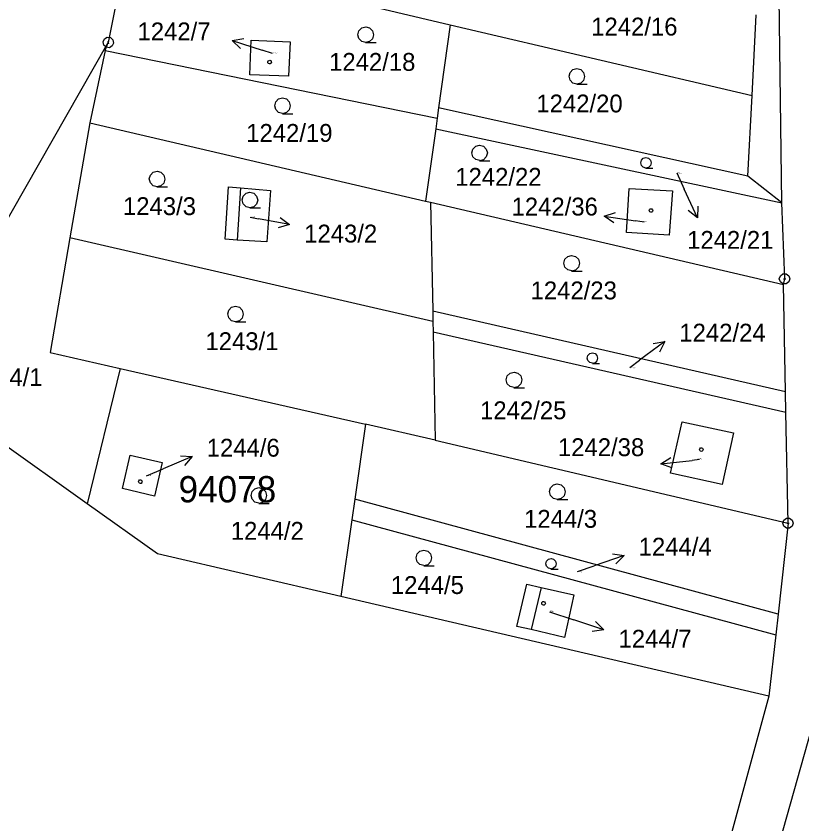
# Model space of a CAD drawing. Extents: x -806774 to -803680, y -1151731 to -1150053.
# Drawn here: x -803855.9 to -803781.2, y -1150682 to -1150605.2 of the extents above; entities that cross this region are included whole.
import ezdxf

# ---------------------------------------------------------------- set-up
doc = ezdxf.new("R2010")
doc.units = 0
for name, color, linetype in [('1', 7, 'Continuous'), ('11', 7, 'Continuous'), ('12', 7, 'Continuous'), ('2', 7, 'Continuous'), ('3', 7, 'Continuous'), ('4', 7, 'Continuous'), ('5', 7, 'Continuous'), ('7', 7, 'Continuous'), ('8', 7, 'Continuous')]:
    doc.layers.add(name, color=color, linetype=linetype)

msp = doc.modelspace()

# ---------------------------------------------------------------- linework, layer by layer
at = {"layer": '1'}
for p, q in [((-803845.41, -1150598.72), (-803847.18, -1150607.67)), ((-803783.05, -1150622.92), (-803783.39, -1150598.76)), ((-803822.55, -1150604.1), (-803814.62, -1150605.97)), ((-803785.89, -1150612.72), (-803785.49, -1150605.04)), ((-803814.62, -1150605.97), (-803815.74, -1150613.89)), ((-803814.62, -1150605.97), (-803785.89, -1150612.72)), ((-803865.58, -1150639.91), (-803847.18, -1150607.67)), ((-803847.47, -1150608.42), (-803847.18, -1150607.67)), ((-803833.69, -1150610.73), (-803833.57, -1150607.45)), ((-803833.57, -1150607.45), (-803829.86, -1150607.61)), ((-803829.86, -1150607.61), (-803830.01, -1150610.88)), ((-803847.47, -1150608.42), (-803848.93, -1150615.31)), ((-803847.47, -1150608.42), (-803815.87, -1150614.85)), ((-803830.01, -1150610.88), (-803833.69, -1150610.73)), ((-803786.3, -1150620.37), (-803785.89, -1150612.72)), ((-803815.74, -1150613.89), (-803815.87, -1150614.85)), ((-803786.3, -1150620.37), (-803815.74, -1150613.89)), ((-803815.87, -1150614.85), (-803816.01, -1150615.87)), ((-803848.93, -1150615.31), (-803850.82, -1150626.24)), ((-803848.93, -1150615.31), (-803816.99, -1150622.76)), ((-803816.01, -1150615.87), (-803816.99, -1150622.76)), ((-803816.01, -1150615.87), (-803783.05, -1150622.92)), ((-803783.05, -1150622.92), (-803786.3, -1150620.37)), ((-803836.05, -1150626.39), (-803835.72, -1150621.41)), ((-803835.72, -1150621.41), (-803834.58, -1150621.51)), ((-803834.58, -1150621.51), (-803831.74, -1150621.75)), ((-803831.74, -1150621.75), (-803832.09, -1150626.64)), ((-803797.86, -1150625.76), (-803797.59, -1150621.57)), ((-803797.59, -1150621.57), (-803793.46, -1150621.79)), ((-803793.46, -1150621.79), (-803793.78, -1150625.99)), ((-803816.99, -1150622.76), (-803816.5, -1150622.87)), ((-803816.5, -1150622.87), (-803816.29, -1150633.21)), ((-803816.5, -1150622.87), (-803782.9, -1150630.7)), ((-803782.79, -1150630.17), (-803783.05, -1150622.92)), ((-803850.82, -1150626.24), (-803852.71, -1150637.17)), ((-803816.27, -1150634.23), (-803850.82, -1150626.24)), ((-803834.92, -1150626.47), (-803836.05, -1150626.39)), ((-803832.09, -1150626.64), (-803834.92, -1150626.47)), ((-803793.78, -1150625.99), (-803797.86, -1150625.76)), ((-803782.9, -1150630.7), (-803782.79, -1150630.17)), ((-803782.71, -1150640.88), (-803782.9, -1150630.7)), ((-803816.29, -1150633.21), (-803816.27, -1150634.23)), ((-803816.29, -1150633.21), (-803782.71, -1150640.88)), ((-803816.27, -1150634.23), (-803816.26, -1150635.22)), ((-803816.26, -1150635.22), (-803816.05, -1150645.51)), ((-803782.67, -1150642.88), (-803816.26, -1150635.22)), ((-803852.71, -1150637.17), (-803846.03, -1150638.68)), ((-803846.03, -1150638.68), (-803849.18, -1150651.58)), ((-803846.03, -1150638.68), (-803822.68, -1150643.99)), ((-803849.18, -1150651.58), (-803864.14, -1150640.93)), ((-803782.67, -1150642.88), (-803782.71, -1150640.88)), ((-803782.47, -1150653.42), (-803782.67, -1150642.88)), ((-803822.68, -1150643.99), (-803823.71, -1150651.14)), ((-803816.05, -1150645.51), (-803822.68, -1150643.99)), ((-803793.67, -1150648.66), (-803792.54, -1150643.75)), ((-803792.54, -1150643.75), (-803787.65, -1150644.82)), ((-803787.65, -1150644.82), (-803788.75, -1150649.74)), ((-803816.05, -1150645.51), (-803782.47, -1150653.42)), ((-803845.83, -1150650.12), (-803845.09, -1150646.95)), ((-803845.09, -1150646.95), (-803842.04, -1150647.64)), ((-803842.04, -1150647.64), (-803842.79, -1150650.83)), ((-803788.75, -1150649.74), (-803793.67, -1150648.66)), ((-803842.79, -1150650.83), (-803845.83, -1150650.12)), ((-803842.49, -1150656.34), (-803849.18, -1150651.58)), ((-803823.71, -1150651.14), (-803824, -1150653.1)), ((-803783.42, -1150662.06), (-803823.71, -1150651.14)), ((-803824, -1150653.1), (-803825.05, -1150660.39)), ((-803824, -1150653.1), (-803783.64, -1150664.03)), ((-803782.47, -1150653.42), (-803783.42, -1150662.06)), ((-803825.05, -1150660.39), (-803842.49, -1150656.34)), ((-803808.28, -1150663.23), (-803807.34, -1150659.2)), ((-803807.34, -1150659.2), (-803805.97, -1150659.52)), ((-803805.97, -1150659.52), (-803802.86, -1150660.22)), ((-803802.86, -1150660.22), (-803803.74, -1150664.29)), ((-803784.29, -1150669.87), (-803825.05, -1150660.39)), ((-803783.42, -1150662.06), (-803783.64, -1150664.03)), ((-803806.93, -1150663.53), (-803808.28, -1150663.23)), ((-803803.74, -1150664.29), (-803806.93, -1150663.53)), ((-803783.64, -1150664.03), (-803784.29, -1150669.87)), ((-803784.29, -1150669.87), (-803800.37, -1150728.46)), ((-803785.39, -1150691.33), (-803779.86, -1150671.69))]:
    msp.add_line(p, q, dxfattribs=at)
at = {"layer": '12'}
for p, q in [((-803833.69, -1150610.73), (-803833.57, -1150607.45)), ((-803833.57, -1150607.45), (-803829.86, -1150607.61)), ((-803829.86, -1150607.61), (-803830.01, -1150610.88)), ((-803830.01, -1150610.88), (-803833.69, -1150610.73)), ((-803797.86, -1150625.76), (-803797.59, -1150621.57)), ((-803797.59, -1150621.57), (-803793.46, -1150621.79)), ((-803793.46, -1150621.79), (-803793.78, -1150625.99)), ((-803793.78, -1150625.99), (-803797.86, -1150625.76)), ((-803793.67, -1150648.66), (-803792.54, -1150643.75)), ((-803792.54, -1150643.75), (-803787.65, -1150644.82)), ((-803787.65, -1150644.82), (-803788.75, -1150649.74)), ((-803845.83, -1150650.12), (-803845.09, -1150646.95)), ((-803845.09, -1150646.95), (-803842.04, -1150647.64)), ((-803842.04, -1150647.64), (-803842.79, -1150650.83)), ((-803788.75, -1150649.74), (-803793.67, -1150648.66)), ((-803842.79, -1150650.83), (-803845.83, -1150650.12)), ((-803805.97, -1150659.52), (-803806.93, -1150663.53)), ((-803805.97, -1150659.52), (-803802.86, -1150660.22)), ((-803802.86, -1150660.22), (-803803.74, -1150664.29)), ((-803803.74, -1150664.29), (-803806.93, -1150663.53))]:
    msp.add_line(p, q, dxfattribs=at)
at = {"layer": '3'}
for points in [[(-803822.66, -1150607.66), (-803823.04, -1150607.56), (-803823.31, -1150607.29), (-803823.41, -1150606.92), (-803823.31, -1150606.55), (-803823.04, -1150606.28), (-803822.67, -1150606.18), (-803822.3, -1150606.28), (-803822.03, -1150606.55), (-803821.93, -1150606.93), (-803822.03, -1150607.31), (-803822.3, -1150607.58), (-803822.68, -1150607.68), (-803821.68, -1150607.68)], [(-803802.56, -1150611.62), (-803802.94, -1150611.52), (-803803.21, -1150611.25), (-803803.31, -1150610.88), (-803803.21, -1150610.51), (-803802.94, -1150610.24), (-803802.57, -1150610.14), (-803802.2, -1150610.24), (-803801.93, -1150610.51), (-803801.83, -1150610.89), (-803801.93, -1150611.27), (-803802.2, -1150611.54), (-803802.58, -1150611.64), (-803801.58, -1150611.64)], [(-803830.58, -1150614.42), (-803830.96, -1150614.32), (-803831.23, -1150614.05), (-803831.33, -1150613.68), (-803831.23, -1150613.31), (-803830.96, -1150613.04), (-803830.59, -1150612.94), (-803830.22, -1150613.04), (-803829.95, -1150613.31), (-803829.85, -1150613.69), (-803829.95, -1150614.07), (-803830.22, -1150614.34), (-803830.6, -1150614.44), (-803829.6, -1150614.44)], [(-803811.82, -1150618.91), (-803812.2, -1150618.81), (-803812.47, -1150618.54), (-803812.57, -1150618.17), (-803812.47, -1150617.8), (-803812.2, -1150617.53), (-803811.83, -1150617.43), (-803811.46, -1150617.53), (-803811.19, -1150617.8), (-803811.09, -1150618.18), (-803811.19, -1150618.56), (-803811.46, -1150618.83), (-803811.84, -1150618.93), (-803810.84, -1150618.93)], [(-803795.99, -1150619.61), (-803796.245, -1150619.543), (-803796.426, -1150619.362), (-803796.492, -1150619.114), (-803796.426, -1150618.866), (-803796.245, -1150618.685), (-803795.997, -1150618.618), (-803795.749, -1150618.685), (-803795.568, -1150618.866), (-803795.501, -1150619.121), (-803795.568, -1150619.376), (-803795.749, -1150619.556), (-803796.003, -1150619.623), (-803795.333, -1150619.623)], [(-803842.52, -1150621.39), (-803842.9, -1150621.29), (-803843.17, -1150621.02), (-803843.27, -1150620.65), (-803843.17, -1150620.28), (-803842.9, -1150620.01), (-803842.53, -1150619.91), (-803842.16, -1150620.01), (-803841.89, -1150620.28), (-803841.79, -1150620.66), (-803841.89, -1150621.04), (-803842.16, -1150621.31), (-803842.54, -1150621.41), (-803841.54, -1150621.41)], [(-803833.68, -1150623.39), (-803834.06, -1150623.29), (-803834.33, -1150623.02), (-803834.43, -1150622.65), (-803834.33, -1150622.28), (-803834.06, -1150622.01), (-803833.69, -1150621.91), (-803833.32, -1150622.01), (-803833.05, -1150622.28), (-803832.95, -1150622.66), (-803833.05, -1150623.04), (-803833.32, -1150623.31), (-803833.7, -1150623.41), (-803832.7, -1150623.41)], [(-803803.06, -1150629.41), (-803803.44, -1150629.31), (-803803.71, -1150629.04), (-803803.81, -1150628.67), (-803803.71, -1150628.3), (-803803.44, -1150628.03), (-803803.07, -1150627.93), (-803802.7, -1150628.03), (-803802.43, -1150628.3), (-803802.33, -1150628.68), (-803802.43, -1150629.06), (-803802.7, -1150629.33), (-803803.08, -1150629.43), (-803802.08, -1150629.43)], [(-803835.05, -1150634.24), (-803835.43, -1150634.14), (-803835.7, -1150633.87), (-803835.8, -1150633.5), (-803835.7, -1150633.13), (-803835.43, -1150632.86), (-803835.06, -1150632.76), (-803834.69, -1150632.86), (-803834.42, -1150633.13), (-803834.32, -1150633.51), (-803834.42, -1150633.89), (-803834.69, -1150634.16), (-803835.07, -1150634.26), (-803834.07, -1150634.26)], [(-803801.08, -1150638.19), (-803801.335, -1150638.123), (-803801.515, -1150637.942), (-803801.582, -1150637.694), (-803801.515, -1150637.446), (-803801.335, -1150637.265), (-803801.087, -1150637.198), (-803800.839, -1150637.265), (-803800.658, -1150637.446), (-803800.591, -1150637.701), (-803800.658, -1150637.955), (-803800.839, -1150638.136), (-803801.093, -1150638.203), (-803800.423, -1150638.203)], [(-803808.54, -1150640.51), (-803808.92, -1150640.41), (-803809.19, -1150640.14), (-803809.29, -1150639.77), (-803809.19, -1150639.4), (-803808.92, -1150639.13), (-803808.55, -1150639.03), (-803808.18, -1150639.13), (-803807.91, -1150639.4), (-803807.81, -1150639.78), (-803807.91, -1150640.16), (-803808.18, -1150640.43), (-803808.56, -1150640.53), (-803807.56, -1150640.53)], [(-803832.83, -1150651.51), (-803833.21, -1150651.41), (-803833.48, -1150651.14), (-803833.58, -1150650.77), (-803833.48, -1150650.4), (-803833.21, -1150650.13), (-803832.84, -1150650.03), (-803832.47, -1150650.13), (-803832.2, -1150650.4), (-803832.1, -1150650.78), (-803832.2, -1150651.16), (-803832.47, -1150651.43), (-803832.85, -1150651.53), (-803831.85, -1150651.53)], [(-803804.42, -1150651.15), (-803804.8, -1150651.05), (-803805.07, -1150650.78), (-803805.17, -1150650.41), (-803805.07, -1150650.04), (-803804.8, -1150649.77), (-803804.43, -1150649.67), (-803804.06, -1150649.77), (-803803.79, -1150650.04), (-803803.69, -1150650.42), (-803803.79, -1150650.8), (-803804.06, -1150651.07), (-803804.44, -1150651.17), (-803803.44, -1150651.17)], [(-803817.13, -1150657.45), (-803817.51, -1150657.35), (-803817.78, -1150657.08), (-803817.88, -1150656.71), (-803817.78, -1150656.34), (-803817.51, -1150656.07), (-803817.14, -1150655.97), (-803816.77, -1150656.07), (-803816.5, -1150656.34), (-803816.4, -1150656.72), (-803816.5, -1150657.1), (-803816.77, -1150657.37), (-803817.15, -1150657.47), (-803816.15, -1150657.47)], [(-803805.02, -1150657.76), (-803805.275, -1150657.693), (-803805.456, -1150657.512), (-803805.523, -1150657.264), (-803805.456, -1150657.016), (-803805.275, -1150656.835), (-803805.027, -1150656.768), (-803804.779, -1150656.835), (-803804.598, -1150657.016), (-803804.531, -1150657.271), (-803804.598, -1150657.525), (-803804.779, -1150657.706), (-803805.033, -1150657.773), (-803804.363, -1150657.773)]]:
    msp.add_lwpolyline(points, dxfattribs=at)
at = {"layer": '4'}
for p, q in [((-803834.58, -1150621.51), (-803834.92, -1150626.47)), ((-803805.97, -1150659.52), (-803806.93, -1150663.53))]:
    msp.add_line(p, q, dxfattribs=at)
at = {"layer": '5'}
for points in [[(-803831.989, -1150609.514), (-803831.96, -1150609.416), (-803831.866, -1150609.375), (-803831.804, -1150609.361), (-803831.716, -1150609.389), (-803831.654, -1150609.475), (-803831.651, -1150609.546), (-803831.689, -1150609.633), (-803831.754, -1150609.687), (-803831.836, -1150609.699), (-803831.924, -1150609.671), (-803831.986, -1150609.585)], [(-803795.52, -1150623.48), (-803795.42, -1150623.5), (-803795.37, -1150623.59), (-803795.35, -1150623.65), (-803795.37, -1150623.74), (-803795.45, -1150623.81), (-803795.52, -1150623.82), (-803795.61, -1150623.79), (-803795.67, -1150623.73), (-803795.69, -1150623.65), (-803795.67, -1150623.56), (-803795.59, -1150623.49)], [(-803790.72, -1150646.24), (-803790.62, -1150646.26), (-803790.57, -1150646.35), (-803790.55, -1150646.41), (-803790.57, -1150646.5), (-803790.65, -1150646.57), (-803790.72, -1150646.58), (-803790.81, -1150646.55), (-803790.87, -1150646.49), (-803790.89, -1150646.41), (-803790.87, -1150646.32), (-803790.79, -1150646.25)], [(-803844.12, -1150649.29), (-803844.02, -1150649.31), (-803843.97, -1150649.4), (-803843.95, -1150649.46), (-803843.97, -1150649.55), (-803844.05, -1150649.62), (-803844.12, -1150649.63), (-803844.21, -1150649.6), (-803844.27, -1150649.54), (-803844.29, -1150649.46), (-803844.27, -1150649.37), (-803844.19, -1150649.3)], [(-803805.74, -1150660.87), (-803805.64, -1150660.89), (-803805.59, -1150660.98), (-803805.57, -1150661.04), (-803805.59, -1150661.13), (-803805.67, -1150661.2), (-803805.74, -1150661.21), (-803805.83, -1150661.18), (-803805.89, -1150661.12), (-803805.91, -1150661.04), (-803805.89, -1150660.95), (-803805.81, -1150660.88)]]:
    msp.add_lwpolyline(points, close=True, dxfattribs=at)
at = {"layer": '7'}
for p, q in [((-803835.386, -1150607.463), (-803832.53, -1150608.38)), ((-803831.53, -1150608.7), (-803832.53, -1150608.38)), ((-803793.07, -1150620.08), (-803792.36, -1150621.62)), ((-803791.1, -1150624.343), (-803792.36, -1150621.62)), ((-803833.67, -1150624.29), (-803832.87, -1150624.44)), ((-803829.923, -1150624.999), (-803832.87, -1150624.44)), ((-803799.957, -1150624.185), (-803796.99, -1150624.63)), ((-803796.16, -1150624.76), (-803796.99, -1150624.63)), ((-803794.206, -1150636.129), (-803796.62, -1150637.91)), ((-803797.53, -1150638.58), (-803796.62, -1150637.91)), ((-803839.198, -1150647.08), (-803841.96, -1150648.25)), ((-803794.572, -1150647.754), (-803791.59, -1150647.43)), ((-803790.89, -1150647.35), (-803791.59, -1150647.43)), ((-803843.54, -1150648.92), (-803841.96, -1150648.25)), ((-803798.08, -1150656.495), (-803800.92, -1150657.46)), ((-803802.5, -1150658), (-803800.92, -1150657.46)), ((-803805.17, -1150661.84), (-803802.85, -1150662.61)), ((-803800.004, -1150663.558), (-803802.85, -1150662.61))]:
    msp.add_line(p, q, dxfattribs=at)
for points in [[(-803834.587, -1150608.244), (-803835.386, -1150607.463), (-803834.281, -1150607.292)], [(-803791.066, -1150623.225), (-803791.1, -1150624.343), (-803791.974, -1150623.645)], [(-803799.042, -1150624.828), (-803799.957, -1150624.185), (-803798.894, -1150623.839)], [(-803830.812, -1150624.321), (-803829.923, -1150624.999), (-803830.998, -1150625.304)], [(-803795.307, -1150636.32), (-803794.206, -1150636.129), (-803794.714, -1150637.125)], [(-803840.313, -1150647.01), (-803839.198, -1150647.08), (-803839.923, -1150647.93)], [(-803793.524, -1150648.143), (-803794.572, -1150647.754), (-803793.632, -1150647.149)], [(-803799.187, -1150656.343), (-803798.08, -1150656.495), (-803798.865, -1150657.29)], [(-803800.794, -1150662.767), (-803800.004, -1150663.558), (-803801.11, -1150663.716)]]:
    msp.add_lwpolyline(points, dxfattribs=at)
at = {"layer": '8'}
for p, q in [((-803847.206, -1150607.553), (-803847.154, -1150607.787)), ((-803782.91, -1150630.17), (-803782.67, -1150630.17)), ((-803782.59, -1150653.42), (-803782.35, -1150653.42))]:
    msp.add_line(p, q, dxfattribs=at)
for points in [[(-803846.679, -1150607.712), (-803846.8, -1150607.995), (-803847.061, -1150608.156), (-803847.366, -1150608.121), (-803847.596, -1150607.917), (-803847.664, -1150607.614), (-803847.543, -1150607.331), (-803847.281, -1150607.17), (-803846.977, -1150607.204), (-803846.746, -1150607.409)], [(-803782.64, -1150629.69), (-803782.39, -1150629.87), (-803782.29, -1150630.16), (-803782.39, -1150630.45), (-803782.64, -1150630.63), (-803782.95, -1150630.63), (-803783.2, -1150630.45), (-803783.3, -1150630.16), (-803783.2, -1150629.87), (-803782.95, -1150629.69)], [(-803782.32, -1150652.94), (-803782.07, -1150653.12), (-803781.97, -1150653.41), (-803782.07, -1150653.7), (-803782.32, -1150653.88), (-803782.63, -1150653.88), (-803782.88, -1150653.7), (-803782.98, -1150653.41), (-803782.88, -1150653.12), (-803782.63, -1150652.94)]]:
    msp.add_lwpolyline(points, close=True, dxfattribs=at)

# ---------------------------------------------------------------- texts
at = {"layer": '11'}
msp.add_text('94078', height=2.5, dxfattribs=at).set_placement((-803840.486, -1150651.43))
at = {"layer": '2'}
for s, height, p in [('1242/16', 1.7, (-803801.207, -1150607)), ('1242/7', 0.1, (-803831.507, -1150608.7)), ('1242/18', 1.7, (-803826.157, -1150610.36)), ('1242/20', 1.7, (-803806.427, -1150614.32)), ('1242/19', 1.7, (-803834.047, -1150617.12)), ('1242/22', 1.7, (-803814.147, -1150621.3)), ('1243/3', 1.7, (-803845.777, -1150624.09)), ('1243/2', 0.1, (-803833.666, -1150624.29)), ('1242/36', 0.1, (-803796.436, -1150624.76)), ('1242/23', 1.7, (-803806.977, -1150632.11)), ('1243/1', 1.7, (-803837.927, -1150636.94)), ('1244/1', 1.7, (-803860.377, -1150640.36)), ('1242/25', 1.7, (-803811.787, -1150643.52)), ('1242/38', 0.1, (-803791.168, -1150647.35)), ('1244/6', 0.1, (-803843.517, -1150648.92)), ('1244/3', 1.7, (-803807.597, -1150653.85)), ('1244/2', 1.7, (-803835.517, -1150654.99)), ('1244/5', 1.7, (-803820.277, -1150660.15)), ('1244/7', 0.1, (-803805.147, -1150661.84))]:
    msp.add_text(s, height=height, dxfattribs=at).set_placement(p)
for s, rotation, p in [('1242/21', 347.38431, (-803793.047, -1150620.085)), ('1242/24', 347.38431, (-803797.507, -1150638.585)), ('1244/4', 344.17575, (-803802.478, -1150658.006))]:
    msp.add_text(s, height=0.1, rotation=rotation, dxfattribs=at).set_placement(p)
at = {"layer": '7'}
for s, p in [('1242/7', (-803844.391, -1150607.46)), ('1242/36', (-803808.788, -1150624.13)), ('1243/2', (-803828.527, -1150626.7)), ('1242/21', (-803792.077, -1150627.3)), ('1242/24', (-803792.817, -1150636.13)), ('1244/6', (-803837.807, -1150647.08)), ('1242/38', (-803804.374, -1150647.03)), ('1244/4', (-803796.687, -1150656.5)), ('1244/7', (-803798.607, -1150665.26))]:
    msp.add_text(s, height=1.7, dxfattribs=at).set_placement(p)

doc.saveas('drawing.dxf')
